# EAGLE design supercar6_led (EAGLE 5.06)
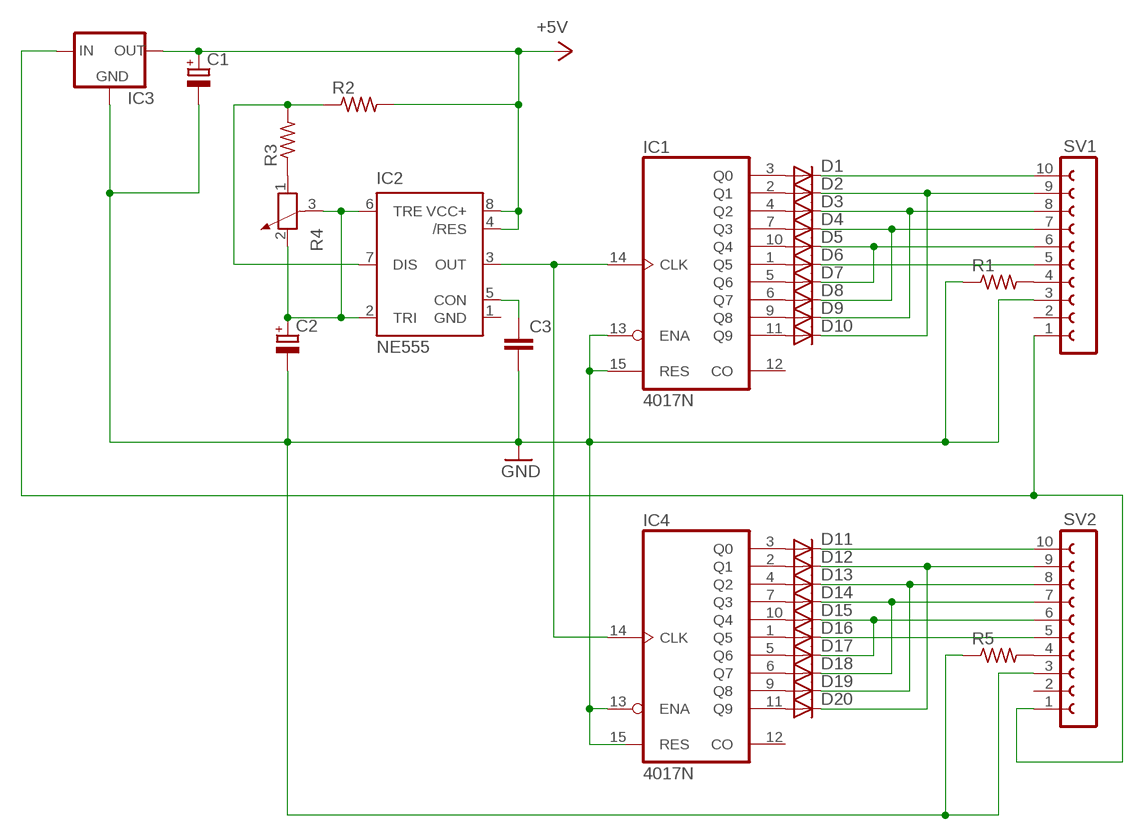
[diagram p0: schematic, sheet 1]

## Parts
C1  CPOL-EUE2.5-7  [E2,5-7]
C2  CPOL-EUE2.5-7  [E2,5-7]
C3  C-EU050-025X075  [C050-025X075]
D1  1N4004  [DO41-10]
D2  1N4004  [DO41-10]
D3  1N4004  [DO41-10]
D4  1N4004  [DO41-10]
D5  1N4004  [DO41-10]
D6  1N4004  [DO41-10]
D7  1N4004  [DO41-10]
D8  1N4004  [DO41-10]
D9  1N4004  [DO41-10]
D10  1N4004  [DO41-10]
D11  1N4004  [DO41-10]
D12  1N4004  [DO41-10]
D13  1N4004  [DO41-10]
D14  1N4004  [DO41-10]
D15  1N4004  [DO41-10]
D16  1N4004  [DO41-10]
D17  1N4004  [DO41-10]
D18  1N4004  [DO41-10]
D19  1N4004  [DO41-10]
D20  1N4004  [DO41-10]
IC1  4017N  [DIL16]
IC2  NE555  [DIL-08]
IC3  78XXS  [78XXS]
IC4  4017N  [DIL16]
R1  R-US_0207/10  [0207/10]
R2  R-US_0207/10  [0207/10]
R3  R-US_0207/10  [0207/10]
R4  POTENTIOMETER_PT-10S  [PT-10S]
R5  R-US_0207/10  [0207/10]
SV1  FE10-1  [FE10]
SV2  FE10-1  [FE10]

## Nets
N$1: D1.A IC1.3(Q0)
N$2: D2.A IC1.2(Q1)
N$3: D3.A IC1.4(Q2)
N$4: D4.A IC1.7(Q3)
N$5: D5.A IC1.10(Q4)
N$6: D6.A IC1.1(Q5)
N$7: D7.A IC1.5(Q6)
N$8: D8.A IC1.6(Q7)
N$9: D9.A IC1.9(Q8)
N$10: D10.A IC1.11(Q9)
N$11: IC2.6(TRE) R4.3
N$12: R3.1 R4.1
N$13: IC2.7(DIS) R2.1 R3.2
N$14: D1.C SV1.10
N$15: C2.+ IC2.2(TRI) R4.2
N$16: D11.A IC4.3(Q0)
N$17: IC1.14(CLK) IC2.3(OUT) IC4.14(CLK)
N$18: D2.C D10.C SV1.9
N$19: C3.1 IC2.5(CON)
N$20: D3.C D9.C SV1.8
N$21: D4.C D8.C SV1.7
N$22: D5.C D7.C SV1.6
N$23: D6.C SV1.5
N$24: D12.A IC4.2(Q1)
N$25: D13.A IC4.4(Q2)
N$26: D14.A IC4.7(Q3)
N$27: D15.A IC4.10(Q4)
N$28: R1.2 SV1.4
N$29: D16.A IC4.1(Q5)
N$30: D17.A IC4.5(Q6)
N$31: D18.A IC4.6(Q7)
N$32: D19.A IC4.9(Q8)
N$33: IC3.IN SV1.1 SV2.1
N$34: D20.A IC4.11(Q9)
N$35: R5.2 SV2.4
N$38: D11.C SV2.10
N$39: D12.C D20.C SV2.9
N$40: D13.C D19.C SV2.8
N$41: D14.C D18.C SV2.7
N$42: D15.C D17.C SV2.6
N$43: D16.C SV2.5
VDD: C1.+ IC2.4(/RES) IC2.8(VCC+) IC3.OUT R2.2 ; supply symbol labelled +5V
VSS: C1.- C2.- C3.2 IC1.13(ENA) IC1.15(RES) IC3.GND IC4.13(ENA) R1.1 R5.1 SV1.3 SV2.3 ; supply symbol labelled GND
Unconnected: IC1.12(CO) IC4.12(CO) IC4.15(RES) SV1.2 SV2.2

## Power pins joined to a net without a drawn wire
VDD: IC1.16(VDD) IC4.16(VDD)
VSS: IC1.8(VSS) IC2.1(GND) IC4.8(VSS)

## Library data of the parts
C1 C2 = resistor:CPOL-EU: POLARIZED CAPACITOR, European symbol
C3 = resistor:C-EU: CAPACITOR, European symbol
D1-D20 = diode:1N4004: DIODE
IC1 IC4 = 40xx:4017: COUNTER/DIVIDER
IC2 = st-microelectronics:NE555: General purpose bipolar Timer
IC3 = v-reg:78XXS: VOLTAGE REGULATOR
R1-R3 R5 = resistor:R-US_: RESISTOR, American symbol
R4 = rcl:POTENTIOMETER_: Potentiometer
SV1 SV2 = con-lsta:FE10-1: FEMALE HEADER

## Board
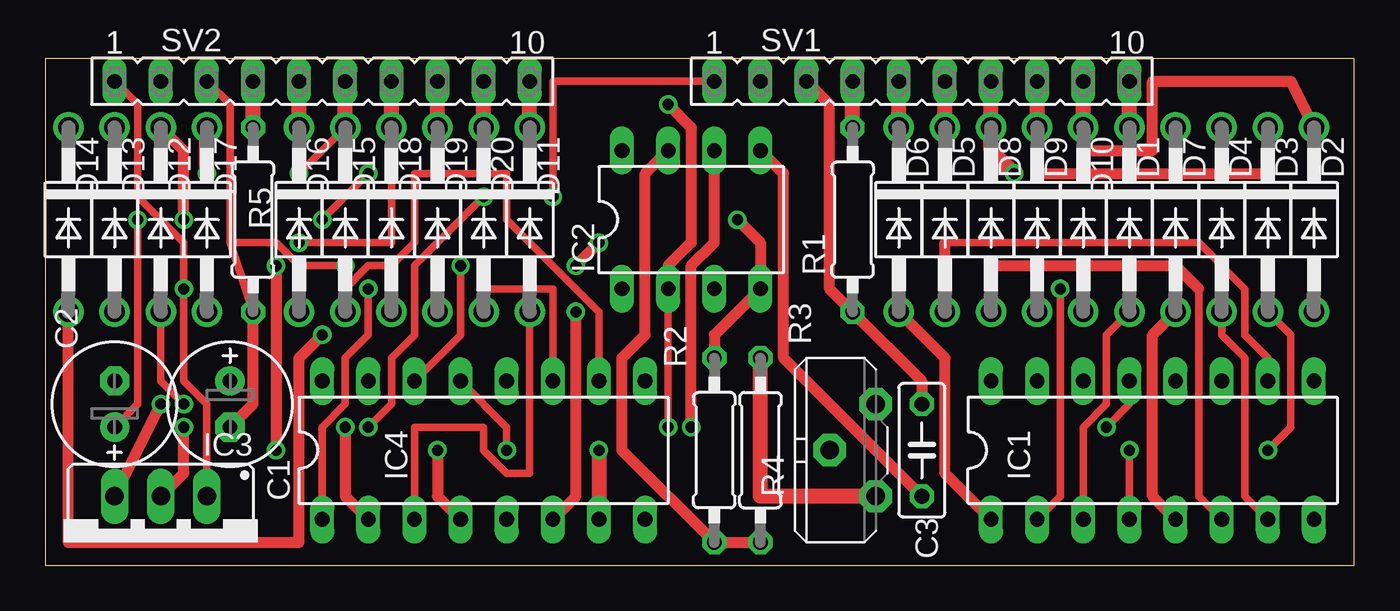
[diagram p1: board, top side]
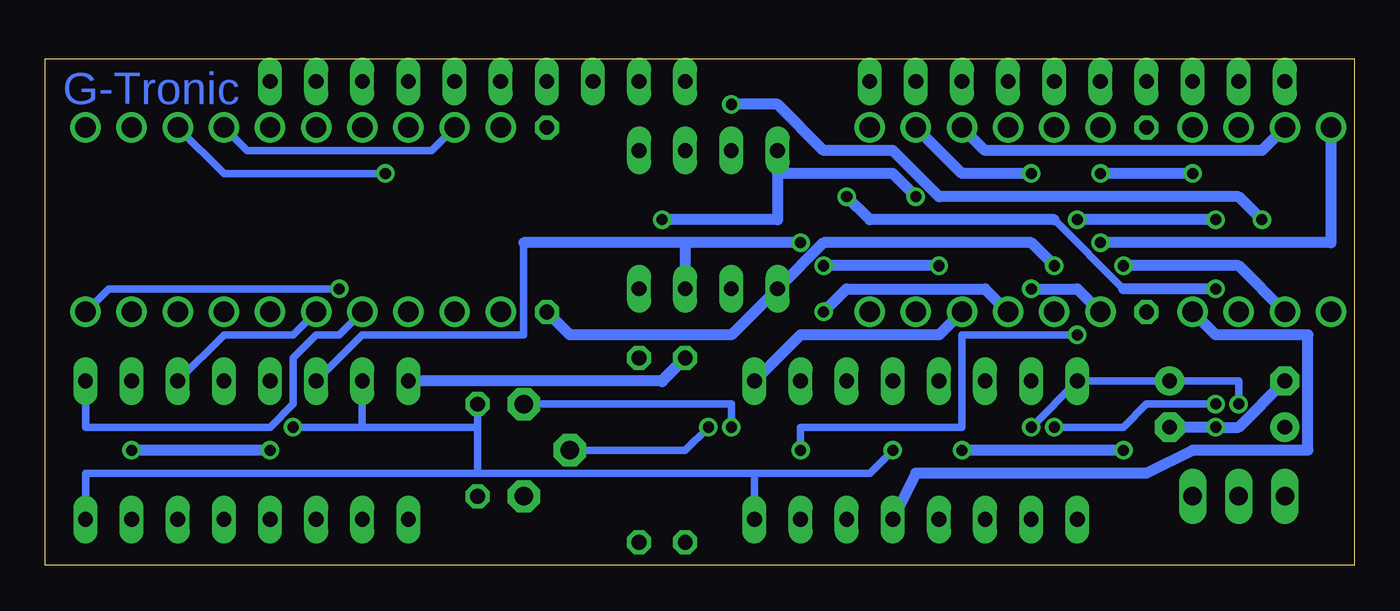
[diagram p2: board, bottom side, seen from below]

Size 72.06 x 27.93 mm. Coordinates in mm from the lower left corner, seen from the top.
Outline: 0,0 72.06,0 72.06,27.93 0,27.93 0,0
Copper layers (1*16): Top 0.035mm / dielectric 1.5mm / Bottom 0.035mm
Design rules "default": minimum track width 10mil, minimum drill 24mil, track to track 8mil, track to pad 8mil, pad to pad 8mil, via to via 8mil, smd to smd 8mil, copper to edge 40mil, drill to drill 8mil, minimum pad ring 10mil, minimum via ring 8mil, stop-mask expansion 4mil, vias tented up to drill 0mil, thermal gap 10mil

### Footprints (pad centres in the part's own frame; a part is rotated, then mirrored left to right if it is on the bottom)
E2,5-7 = drill 0.813 pad 1.6 round: + -1.27,0 | drill 0.813 pad 1.6 octagon: - 1.27,0
C050-025X075 = drill 0.813 octagon: 1 -2.54,0; 2 2.54,0
DO41-10 = drill 1.118 round: A 5.08,0; C -5.08,0
DIL16 = drill 0.813 long: 1 -8.89,-3.81; 2 -6.35,-3.81; 3 -3.81,-3.81; 4 -1.27,-3.81; 5 1.27,-3.81; 6 3.81,-3.81; 7 6.35,-3.81; 8 8.89,-3.81; 9 8.89,3.81; 10 6.35,3.81; 11 3.81,3.81; 12 1.27,3.81; 13 -1.27,3.81; 14 -3.81,3.81; 15 -6.35,3.81; 16 -8.89,3.81
DIL-08 = drill 0.813 long: 1 -3.81,-3.81; 2 -1.27,-3.81; 3 1.27,-3.81; 4 3.81,-3.81; 5 3.81,3.81; 6 1.27,3.81; 7 -1.27,3.81; 8 -3.81,3.81
78XXS = drill 1.016 long: GND 0,-2.54; IN -2.54,-2.54; OUT 2.54,-2.54
0207/10 = drill 0.813 octagon: 1 -5.08,0; 2 5.08,0
PT-10S = drill 1.016 pad 1.778 octagon: 1 -2.54,-1.27; 2 2.54,-1.27; 3 0,1.27
FE10 = drill 0.813 long: 1 -11.43,0; 2 -8.89,0; 3 -6.35,0; 4 -3.81,0; 5 -1.27,0; 6 1.27,0; 7 3.81,0; 8 6.35,0; 9 8.89,0; 10 11.43,0

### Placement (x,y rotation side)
C1  10.16,8.89 270 top
C2  3.81,8.89 90 top
C3  48.26,6.35 90 top
D1  59.69,19.05 270 top
D2  69.85,19.05 270 top
D3  67.31,19.05 270 top
D4  64.77,19.05 270 top
D5  49.53,19.05 270 top
D6  46.99,19.05 270 top
D7  62.23,19.05 270 top
D8  52.07,19.05 270 top
D9  54.61,19.05 270 top
D10  57.15,19.05 270 top
D11  26.67,19.05 270 top
D12  6.35,19.05 270 top
D13  3.81,19.05 270 top
D14  1.27,19.05 270 top
D15  16.51,19.05 270 top
D16  13.97,19.05 270 top
D17  8.89,19.05 270 top
D18  19.05,19.05 270 top
D19  21.59,19.05 270 top
D20  24.13,19.05 270 top
IC1  60.96,6.35 0 top
IC2  35.56,19.05 0 top
IC3  6.35,1.27 180 top
IC4  24.13,6.35 0 top
R1  44.45,19.05 90 top
R2  36.83,6.35 90 top
R3  39.37,6.35 270 top
R4  44.45,6.35 90 top
R5  11.43,19.05 90 top
SV1  48.26,26.67 0 top
SV2  15.24,26.67 0 top

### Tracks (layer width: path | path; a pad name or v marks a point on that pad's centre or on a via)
N$1
  Top 0.406: IC1.3 57.15,7.62 58.42,8.89 58.42,12.7 D1.A
N$2  (via drill 0.61)
  Top 0.406: IC1.2 55.88,3.81 v55.88,15.24
  Bottom 0.406: v55.88,15.24 68.58,15.24 D2.A
N$3  (via drill 0.61)
  Top 0.406: IC1.4 v59.69,6.35 | v67.31,6.35 68.58,7.62 68.58,12.7 D3.A
  Bottom 0.61: v59.69,6.35 v67.31,6.35
N$4
  Top 0.406: IC1.7 66.04,3.81 66.04,11.43 64.77,12.7 D4.A
N$5
  Top 0.406: IC1.10 67.31,11.43 66.04,12.7 66.04,15.24 63.5,17.78 49.53,17.78
  Top 0.61: D5.A 49.53,17.78
N$6
  Top 0.61: IC1.1 49.53,5.08 49.53,11.43 D6.A
N$7
  Top 0.61: IC1.5 60.96,3.81 60.96,12.7 D7.A
N$8
  Top 0.406: IC1.6 63.5,3.81 63.5,15.24
  Top 0.61: 63.5,15.24 62.23,16.51 52.07,16.51 D8.A
N$9
  Bottom 0.406: IC1.9 69.85,7.62 59.69,7.62 58.42,8.89 58.42,11.43 57.15,12.7 55.88,12.7 D9.A
N$10
  Bottom 0.406: IC1.11 62.23,12.7 58.42,12.7 D10.A
N$11  (via drill 0.61)
  Top 0.61: IC2.6 36.83,17.78 35.56,16.51 v35.56,7.62
  Bottom 0.406: v35.56,7.62 36.83,6.35 R4.3
N$12
  Top 0.813: R3.1 39.37,3.81 R4.1
N$13
  Top 0.61: R3.2 R2.1 31.75,6.35 31.75,11.43 33.02,12.7 33.02,21.59 IC2.7
N$14
  Top 0.813: D1.C SV1.10
N$15  (via drill 0.61)
  Top 0.406: IC2.2 v34.29,7.62 | C2.+ 5.08,8.89 v5.08,19.05
  Top 0.61: v34.29,25.4 35.56,24.13 35.56,17.78 34.29,16.51 IC2.2
  Bottom 0.406: v34.29,7.62 34.29,8.89 R4.2
  Bottom 0.61: v5.08,19.05 6.35,20.32 22.86,20.32 25.4,22.86 29.21,22.86 31.75,25.4 v34.29,25.4
N$16
  Top 0.406: IC4.3 20.32,7.62 24.13,7.62 24.13,6.35 25.4,5.08 26.67,5.08 D11.A
N$17  (via drill 0.61)
  Top 0.406: IC4.14 22.86,12.7 v22.86,16.51
  Top 0.61: v29.21,16.51 v30.48,17.78
  Bottom 0.406: IC1.14 54.61,12.7 45.72,12.7 45.72,17.78
  Bottom 0.61: v22.86,16.51 v29.21,16.51 | v30.48,17.78 36.83,17.78 | 36.83,17.78 IC2.3 | 36.83,17.78 45.72,17.78
N$18
  Top 0.61: D2.C 68.58,26.67 60.96,26.67 60.96,22.86 57.15,22.86 D10.C
  Top 0.813: D10.C SV1.9
N$19
  Top 0.61: C3.1 40.64,11.43 40.64,21.59 IC2.5
N$20
  Top 0.61: D3.C 67.31,21.59 54.61,21.59 D9.C
  Top 0.813: D9.C SV1.8
N$21  (via drill 0.61)
  Top 0.813: SV1.7 D8.C 52.07,22.86 v53.34,21.59
  Bottom 0.406: D4.C 62.23,21.59 v53.34,21.59
N$22
  Top 0.813: D5.C SV1.6
  Bottom 0.406: D7.C 60.96,22.86 50.8,22.86 D5.C
N$23
  Top 0.813: D6.C SV1.5
N$24  (via drill 0.61)
  Top 0.406: v7.62,8.89 6.35,10.16 D12.A
  Top 0.61: IC4.2 16.51,3.81 v16.51,7.62
  Bottom 0.406: v16.51,7.62 12.7,7.62 11.43,8.89 v7.62,8.89
N$25  (via drill 0.61)
  Top 0.61: IC4.4 21.59,3.81 v21.59,6.35 | v12.7,16.51 v12.7,6.35
  Bottom 0.61: v12.7,6.35 v21.59,6.35 | v12.7,16.51 6.35,16.51 D13.A
N$26  (via drill 0.61)
  Top 0.61: v15.24,12.7 13.97,11.43 13.97,1.27 1.27,1.27 D14.A
  Top 0.813: v30.48,6.35 IC4.7
  Bottom 0.406: v30.48,6.35 30.48,7.62 21.59,7.62 21.59,12.7 v15.24,12.7
N$27
  Top 0.406: IC4.10 30.48,13.97 25.4,19.05 25.4,21.59 24.13,21.59 20.32,21.59 20.32,17.78 19.05,16.51 17.78,16.51 16.51,15.24 D15.A
N$28
  Top 0.813: R1.2 SV1.4
N$29  (via drill 0.61)
  Top 0.406: IC4.1 15.24,7.62 16.51,8.89 16.51,11.43 17.78,12.7 v17.78,15.24
  Bottom 0.61: v17.78,15.24 15.24,15.24 D16.A
N$30
  Bottom 0.61: IC4.5 24.13,5.08 11.43,5.08 8.89,6.35 2.54,6.35 2.54,12.7 7.62,12.7 D17.A
N$31  (via drill 0.61)
  Top 0.61: IC4.6 29.21,3.81 v29.21,13.97
  Bottom 0.61: v29.21,13.97 27.94,15.24 20.32,15.24 D18.A
N$32
  Bottom 0.61: IC4.9 30.48,12.7 22.86,12.7 D19.A
N$33  (via drill 0.61)
  Top 0.406: SV2.1 5.08,25.4 5.08,20.32 7.62,17.78 v7.62,15.24 7.62,10.16 8.89,8.89 IC3.IN | SV1.1 27.94,26.67 v27.94,20.32
  Bottom 0.406: 12.7,15.24 16.51,19.05
  Bottom 0.61: v27.94,20.32 26.67,19.05 16.51,19.05 | v7.62,15.24 12.7,15.24
N$34
  Top 0.406: IC4.11 27.94,15.24 24.13,15.24 D20.A
N$35
  Top 0.813: R5.2 SV2.4
N$38
  Top 0.813: D11.C SV2.10
N$39  (via drill 0.61)
  Top 0.406: v15.24,19.05 v17.78,21.59
  Top 0.61: D12.C 7.62,22.86 v7.62,19.05
  Top 0.813: D20.C SV2.9
  Bottom 0.61: v7.62,19.05 v15.24,19.05 | v17.78,21.59 21.59,21.59 D20.C
N$40
  Top 0.813: D19.C SV2.8
  Bottom 0.61: D13.C 5.08,22.86 20.32,22.86 D19.C
N$41  (via drill 0.61)
  Top 0.406: v13.97,17.78 19.05,17.78 D18.C
  Top 0.813: D18.C SV2.7
  Bottom 0.61: D14.C 1.27,17.78 v13.97,17.78
N$42  (via drill 0.61)
  Top 0.406: v13.97,21.59 D15.C
  Top 0.813: D15.C SV2.6 | v8.89,21.59 D17.C
  Bottom 0.61: v8.89,21.59 v13.97,21.59
N$43
  Top 0.813: D16.C SV2.5
VDD  (via drill 0.61)
  Top 0.406: v17.78,7.62 19.05,8.89 19.05,11.43 20.32,12.7 20.32,16.51 v24.13,20.32
  Top 0.61: IC3.OUT v6.35,8.89 | R2.2 36.83,12.7 IC2.4 39.37,17.78 v38.1,19.05
  Bottom 0.406: v6.35,8.89 6.35,10.16 C1.+ IC4.16 v17.78,7.62
  Bottom 0.61: 38.1,10.16 IC1.16 | 31.75,21.59 31.75,19.05 v38.1,19.05 | 31.75,21.59 IC2.8 | v24.13,20.32 25.4,21.59 31.75,21.59
  Bottom 0.686: R2.2 38.1,10.16
VSS  (via drill 0.61)
  Top 0.406: SV2.3 10.16,25.4 10.16,17.78 | IC4.13 25.4,7.62 v25.4,6.35 | IC1.13 59.69,8.89 v58.42,7.62 | R5.1 10.16,17.78 | 10.16,17.78 12.7,17.78 13.97,16.51 v16.51,16.51
  Top 0.61: R5.1 11.43,8.89 C1.- | IC3.GND 7.62,5.08 v7.62,7.62 | C3.2 48.26,10.16 R1.1 43.18,15.24 43.18,25.4 SV1.3
  Bottom 0.406: 33.02,5.08 IC4.8 | 48.26,5.08 33.02,5.08 | C3.2 48.26,7.62 | 48.26,7.62 48.26,5.08 | v25.4,6.35 26.67,5.08 33.02,5.08 | 54.61,7.62 IC1.15 | 48.26,7.62 54.61,7.62 | 54.61,7.62 v58.42,7.62 | IC1.8 69.85,5.08 48.26,5.08
  Bottom 0.61: C1.- v7.62,7.62 6.35,7.62 C2.- | R1.1 43.18,12.7 34.29,12.7 IC2.1 29.21,17.78 17.78,17.78 v16.51,16.51

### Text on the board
Bottom: G-Tronic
